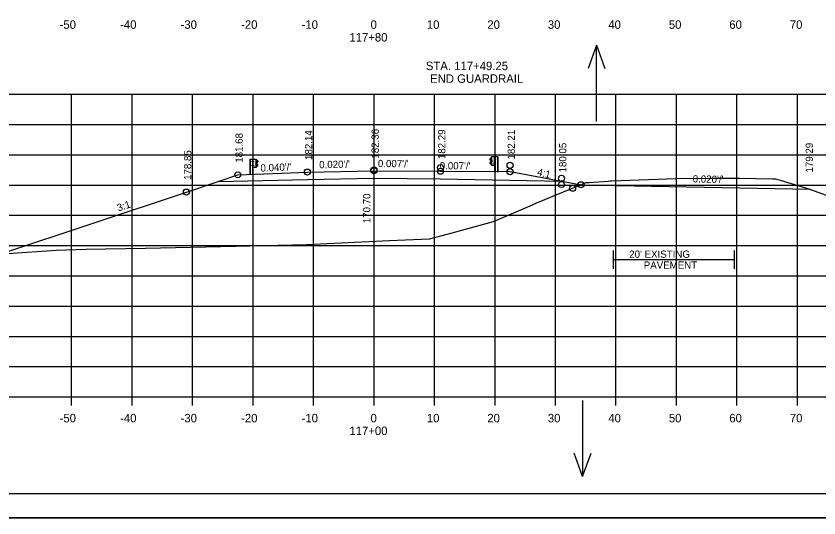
# Model space of a CAD drawing. Extents: x 915787 to 919910, y 133456 to 136717.
# Drawn here: x 916354.8 to 916487.5, y 135376.1 to 135459 of the extents above; entities that cross this region are included whole.
import ezdxf

# ---------------------------------------------------------------- set-up
doc = ezdxf.new("R2010")
doc.units = 0
for name, color, linetype in [('R_Axis', 7, 'Continuous'), ('R_Axis Annot', 7, 'Continuous'), ('R_Border', 7, 'Continuous'), ('R_Drive', 7, 'Continuous'), ('R_Exist Surface', 7, 'Continuous'), ('R_Exist Surface Annot', 7, 'Continuous'), ('R_Fin Surface', 7, 'Continuous'), ('R_Grid', 7, 'Continuous'), ('R_No Plot', 7, 'Continuous'), ('R_Proposed Road', 7, 'Continuous'), ('R_Water', 7, 'Continuous'), ('R_Water Annot', 7, 'Continuous'), ('R_Xsect Elev', 7, 'Continuous'), ('R_Xsect Slope', 7, 'Continuous')]:
    doc.layers.add(name, color=color, linetype=linetype)

msp = doc.modelspace()

# ---------------------------------------------------------------- linework, layer by layer
at = {"layer": 'R_Axis'}
for p, q in [((916273.98, 135396.06), (916553.98, 135396.06)), ((916363.98, 135394.66), (916363.98, 135396.06)), ((916373.98, 135394.66), (916373.98, 135396.06)), ((916383.98, 135394.66), (916383.98, 135396.06)), ((916393.98, 135394.66), (916393.98, 135396.06)), ((916403.98, 135394.66), (916403.98, 135396.06)), ((916413.98, 135394.66), (916413.98, 135396.06)), ((916423.98, 135394.66), (916423.98, 135396.06)), ((916433.98, 135394.66), (916433.98, 135396.06)), ((916443.98, 135394.66), (916443.98, 135396.06)), ((916453.98, 135394.66), (916453.98, 135396.06)), ((916463.98, 135394.66), (916463.98, 135396.06)), ((916473.98, 135394.66), (916473.98, 135396.06)), ((916483.98, 135394.66), (916483.98, 135396.06))]:
    msp.add_line(p, q, dxfattribs=at)
at = {"layer": 'R_Border'}
msp.add_line((916572.16, 135380.06), (916255.98, 135380.06), dxfattribs=at)
at = {"layer": 'R_Exist Surface'}
msp.add_lwpolyline([(916353.45, 135419.75), (916361.45, 135420.29), (916366.41, 135420.44), (916376.19, 135420.61), (916391.14, 135420.98), (916402.82, 135421.24), (916416.55, 135421.87), (916423.16, 135422.2), (916426.28, 135423.02), (916433.75, 135425.02), (916440.16, 135427.79), (916441, 135428.16), (916441.3, 135428.27), (916449.05, 135431.45), (916449.53, 135431.49), (916452.66, 135431.7), (916453.04, 135431.73), (916453.21, 135431.73), (916463.91, 135432.13), (916469.42, 135432.17), (916474.44, 135432.21), (916479.84, 135432.08), (916480.34, 135432.07), (916481.09, 135431.86), (916485.87, 135430.42), (916489.6, 135429.03)], dxfattribs=at)
at = {"layer": 'R_Exist Surface Annot'}
for p, q in [((916453.53, 135420.24), (916453.53, 135417.24)), ((916473.53, 135420.24), (916473.53, 135417.24)), ((916453.53, 135418.74), (916473.53, 135418.74))]:
    msp.add_line(p, q, dxfattribs=at)
at = {"layer": 'R_Fin Surface'}
for points in [[(916352.3, 135419.68), (916382.97, 135429.9), (916388.22, 135431.65), (916391.47, 135432.74), (916402.97, 135433.2), (916413.97, 135433.42), (916424.97, 135433.34), (916436.47, 135433.27), (916448.21, 135431.1), (916486.06, 135430.35)], [(916388.22, 135431.65), (916402.97, 135431.95), (916413.97, 135432.17), (916424.97, 135432.09), (916445.02, 135431.69)]]:
    msp.add_lwpolyline(points, dxfattribs=at)
at = {"layer": 'R_Grid'}
for p, q in [((916273.98, 135446.06), (916553.98, 135446.06)), ((916363.98, 135396.06), (916363.98, 135446.06)), ((916373.98, 135396.06), (916373.98, 135446.06)), ((916383.98, 135396.06), (916383.98, 135446.06)), ((916393.98, 135396.06), (916393.98, 135446.06)), ((916403.98, 135396.06), (916403.98, 135446.06)), ((916413.98, 135396.06), (916413.98, 135446.06)), ((916423.98, 135396.06), (916423.98, 135446.06)), ((916433.98, 135396.06), (916433.98, 135446.06)), ((916443.98, 135396.06), (916443.98, 135446.06)), ((916453.98, 135396.06), (916453.98, 135446.06)), ((916463.98, 135396.06), (916463.98, 135446.06)), ((916473.98, 135396.06), (916473.98, 135446.06)), ((916483.98, 135396.06), (916483.98, 135446.06)), ((916273.98, 135441.06), (916553.98, 135441.06)), ((916273.98, 135436.06), (916553.98, 135436.06)), ((916273.98, 135431.06), (916553.98, 135431.06)), ((916273.98, 135426.06), (916553.98, 135426.06)), ((916273.98, 135421.06), (916553.98, 135421.06)), ((916273.98, 135416.06), (916553.98, 135416.06)), ((916273.98, 135411.06), (916553.98, 135411.06)), ((916273.98, 135406.06), (916553.98, 135406.06)), ((916273.98, 135401.06), (916553.98, 135401.06)), ((916273.98, 135396.06), (916553.98, 135396.06))]:
    msp.add_line(p, q, dxfattribs=at)
at = {"layer": 'R_No Plot'}
msp.add_line((916243.57, 135376.08), (916576.91, 135376.08), dxfattribs=at)
for points in [[(916243.57, 135589.41), (916576.91, 135589.41), (916576.91, 135376.07), (916243.57, 135376.07)], [(916489.9, 135585.52), (916489.9, 135575.64), (916525.63, 135575.64), (916525.63, 135572.72), (916548.83, 135572.72), (916548.83, 135549.5), (916572.16, 135549.5), (916572.16, 135380.06), (916255.98, 135380.06), (916255.98, 135585.52)]]:
    msp.add_lwpolyline(points, close=True, dxfattribs=at)
for centre in [(916402.97, 135433.2), (916402.97, 135433.2), (916413.97, 135433.56), (916413.97, 135433.42), (916424.97, 135433.93), (916424.97, 135433.34), (916436.47, 135434.31), (916436.47, 135433.27), (916391.47, 135432.74), (916391.47, 135432.74), (916444.97, 135432.18), (916444.97, 135431.14), (916446.81, 135430.53), (916448.21, 135431.1), (916382.97, 135429.9), (916382.97, 135429.9)]:
    msp.add_circle(centre, 0.5, dxfattribs=at)
at = {"layer": 'R_Proposed Road'}
for p, q in [((916393.47, 135435.33), (916393.47, 135432.81)), ((916393.5, 135435.33), (916393.5, 135432.81)), ((916393.87, 135434.92), (916393.87, 135435.01)), ((916393.93, 135435.03), (916393.88, 135435.03)), ((916393.93, 135435), (916393.88, 135435)), ((916393.93, 135434.93), (916393.88, 135434.93)), ((916393.93, 135434.9), (916393.88, 135434.9)), ((916393.93, 135434.93), (916393.89, 135434.93)), ((916394, 135435.33), (916393.93, 135435.33)), ((916393.93, 135434.9), (916393.93, 135435.03)), ((916393.97, 135432.81), (916393.97, 135435.33)), ((916394, 135435.33), (916393.99, 135435.33)), ((916394.05, 135434.96), (916394, 135434.96)), ((916394.01, 135435.02), (916394.06, 135435.02)), ((916394.01, 135434.9), (916394.06, 135434.9)), ((916394.06, 135435.02), (916394.06, 135434.9)), ((916394.5, 135433.96), (916394.5, 135435.32)), ((916394.64, 135435.11), (916394.53, 135435.17)), ((916394.63, 135435.1), (916394.54, 135435.15)), ((916394.76, 135434.99), (916394.63, 135435.1)), ((916394.77, 135435.01), (916394.64, 135435.11)), ((916433.14, 135435.38), (916433.27, 135435.48)), ((916433.32, 135435.13), (916433.15, 135435.23)), ((916433.16, 135435.36), (916433.29, 135435.47)), ((916433.33, 135435.15), (916433.16, 135435.26)), ((916433.17, 135434.8), (916433.32, 135434.9)), ((916433.27, 135435.48), (916433.38, 135435.54)), ((916433.29, 135435.47), (916433.38, 135435.52)), ((916433.35, 135434.95), (916433.35, 135435.08)), ((916433.38, 135434.95), (916433.38, 135435.08)), ((916433.42, 135434.33), (916433.42, 135435.69)), ((916433.43, 135434.95), (916433.43, 135435.07)), ((916433.43, 135435.07), (916433.48, 135435.07)), ((916433.43, 135435.04), (916433.48, 135435.04)), ((916433.43, 135434.98), (916433.47, 135434.98)), ((916433.43, 135434.98), (916433.48, 135434.98)), ((916433.43, 135434.95), (916433.48, 135434.95)), ((916433.48, 135434.96), (916433.48, 135435.06)), ((916433.91, 135435.39), (916433.86, 135435.39)), ((916433.86, 135435.39), (916433.86, 135435.27)), ((916433.86, 135435.33), (916433.92, 135435.33)), ((916433.91, 135435.27), (916433.86, 135435.27)), ((916433.92, 135435.7), (916433.92, 135435.7)), ((916433.92, 135435.7), (916433.98, 135435.7)), ((916433.95, 135433.18), (916433.95, 135435.7)), ((916433.99, 135435.27), (916433.99, 135435.4)), ((916433.99, 135435.4), (916434.03, 135435.4)), ((916433.99, 135435.37), (916434.03, 135435.37)), ((916433.99, 135435.3), (916434.03, 135435.3)), ((916433.99, 135435.3), (916434.03, 135435.3)), ((916433.99, 135435.27), (916434.04, 135435.27)), ((916434.04, 135435.29), (916434.04, 135435.38)), ((916434.41, 135435.7), (916434.41, 135433.18)), ((916434.44, 135435.7), (916434.44, 135433.18)), ((916393.86, 135434.23), (916393.86, 135434.32)), ((916393.92, 135434.34), (916393.87, 135434.34)), ((916393.92, 135434.31), (916393.87, 135434.31)), ((916393.92, 135434.24), (916393.87, 135434.24)), ((916393.92, 135434.21), (916393.87, 135434.21)), ((916393.92, 135434.24), (916393.88, 135434.24)), ((916393.92, 135434.21), (916393.92, 135434.34)), ((916394, 135433.96), (916393.96, 135433.96)), ((916394.05, 135434.27), (916394, 135434.27)), ((916394.06, 135434.34), (916394.01, 135434.34)), ((916394.06, 135434.21), (916394.01, 135434.21)), ((916394.06, 135434.21), (916394.06, 135434.34)), ((916394.43, 135434.59), (916394.43, 135434.69)), ((916394.49, 135434.7), (916394.44, 135434.7)), ((916394.49, 135434.67), (916394.44, 135434.67)), ((916394.49, 135434.61), (916394.44, 135434.61)), ((916394.49, 135434.61), (916394.44, 135434.61)), ((916394.49, 135434.58), (916394.44, 135434.58)), ((916394.49, 135434.58), (916394.49, 135434.7)), ((916394.53, 135434.12), (916394.63, 135434.18)), ((916394.53, 135434.1), (916394.65, 135434.16)), ((916394.54, 135434.58), (916394.54, 135434.71)), ((916394.56, 135434.58), (916394.56, 135434.71)), ((916394.58, 135434.78), (916394.76, 135434.89)), ((916394.73, 135434.41), (916394.58, 135434.51)), ((916394.75, 135434.43), (916394.59, 135434.53)), ((916394.6, 135434.76), (916394.77, 135434.86)), ((916394.63, 135434.18), (916394.76, 135434.29)), ((916394.65, 135434.16), (916394.77, 135434.27)), ((916433.27, 135434.53), (916433.14, 135434.64)), ((916433.28, 135434.55), (916433.15, 135434.66)), ((916433.18, 135434.78), (916433.34, 135434.88)), ((916433.38, 135434.47), (916433.27, 135434.53)), ((916433.39, 135434.49), (916433.28, 135434.55)), ((916433.86, 135434.58), (916433.86, 135434.71)), ((916433.86, 135434.71), (916433.91, 135434.71)), ((916433.86, 135434.64), (916433.92, 135434.64)), ((916433.86, 135434.58), (916433.91, 135434.58)), ((916433.92, 135434.33), (916433.95, 135434.33)), ((916434, 135434.58), (916434, 135434.71)), ((916434, 135434.71), (916434.04, 135434.71)), ((916434, 135434.68), (916434.05, 135434.68)), ((916434, 135434.61), (916434.04, 135434.61)), ((916434, 135434.61), (916434.05, 135434.61)), ((916434, 135434.58), (916434.05, 135434.58)), ((916434.05, 135434.6), (916434.05, 135434.69))]:
    msp.add_line(p, q, dxfattribs=at)
for points in [[(916393.47, 135435.33), (916393.93, 135435.33), (916393.93, 135432.81)], [(916434.44, 135435.7), (916433.98, 135435.7), (916433.99, 135433.18)]]:
    msp.add_lwpolyline(points, dxfattribs=at)
for points in [[(916393.87, 135434.99), (916393.87, 135434.93), (916393.85, 135434.93), (916393.85, 135434.99)], [(916393.93, 135435.05), (916393.93, 135434.88), (916393.94, 135434.88), (916393.94, 135435.05)], [(916394.52, 135435.33), (916394.52, 135433.96), (916394, 135433.96), (916394, 135435.33)], [(916394.05, 135435.02), (916394.05, 135434.9), (916394, 135434.9), (916394, 135435.02)], [(916433.39, 135435.7), (916433.39, 135434.33), (916433.92, 135434.33), (916433.92, 135435.7)], [(916433.43, 135435.09), (916433.43, 135434.93), (916433.42, 135434.93), (916433.42, 135435.09)], [(916433.49, 135435.04), (916433.49, 135434.98), (916433.51, 135434.98), (916433.51, 135435.04)], [(916433.86, 135435.39), (916433.86, 135435.27), (916433.92, 135435.27), (916433.92, 135435.39)], [(916433.99, 135435.42), (916433.99, 135435.25), (916433.98, 135435.25), (916433.98, 135435.42)], [(916434.04, 135435.36), (916434.04, 135435.3), (916434.07, 135435.3), (916434.07, 135435.36)], [(916393.86, 135434.31), (916393.86, 135434.24), (916393.84, 135434.24), (916393.84, 135434.31)], [(916393.92, 135434.36), (916393.92, 135434.19), (916393.93, 135434.19), (916393.93, 135434.36)], [(916394.05, 135434.34), (916394.05, 135434.21), (916394, 135434.21), (916394, 135434.34)], [(916394.43, 135434.67), (916394.43, 135434.61), (916394.4, 135434.61), (916394.4, 135434.67)], [(916394.48, 135434.72), (916394.48, 135434.56), (916394.49, 135434.56), (916394.49, 135434.72)], [(916433.86, 135434.71), (916433.86, 135434.58), (916433.92, 135434.58), (916433.92, 135434.71)], [(916434, 135434.73), (916434, 135434.56), (916433.99, 135434.56), (916433.99, 135434.73)], [(916434.05, 135434.68), (916434.05, 135434.61), (916434.08, 135434.61), (916434.08, 135434.68)]]:
    msp.add_lwpolyline(points, close=True, dxfattribs=at)
for centre, radius, start, end in [((916393.9, 135435.01), 0.022, 134.5745, 222.2244), ((916393.97, 135434.96), 0.0922, 159.7423, 200.2577), ((916393.9, 135434.92), 0.025, 140.9334, 216.6234), ((916394.73, 135434.94), 0.062, 299.2499, 57.9783), ((916394.73, 135434.94), 0.0856, 299.2499, 57.9783), ((916433.19, 135435.31), 0.0856, 122.0217, 240.7501), ((916433.19, 135435.31), 0.062, 122.0217, 240.7501), ((916433.36, 135435.01), 0.0453, 93.9303, 257.0446), ((916433.29, 135435.07), 0.0622, 4.9556, 61.894), ((916433.29, 135435.07), 0.0865, 4.9556, 61.894), ((916433.31, 135434.94), 0.0462, 293.1464, 8.2196), ((916433.31, 135434.94), 0.0703, 293.1464, 8.2196), ((916433.46, 135435.06), 0.022, 317.7756, 45.4255), ((916433.39, 135435.01), 0.0922, 339.7423, 20.2577), ((916433.46, 135434.96), 0.025, 323.3766, 39.0666), ((916434.02, 135435.38), 0.022, 317.7756, 45.4255), ((916433.95, 135435.33), 0.0922, 339.7423, 20.2577), ((916434.02, 135435.28), 0.025, 323.3766, 39.0666), ((916393.89, 135434.32), 0.022, 134.5745, 222.2244), ((916393.96, 135434.27), 0.0922, 159.7423, 200.2577), ((916393.89, 135434.23), 0.025, 140.9334, 216.6234), ((916394.45, 135434.69), 0.022, 134.5745, 222.2244), ((916394.52, 135434.64), 0.0922, 159.7423, 200.2577), ((916394.46, 135434.59), 0.025, 140.9334, 216.6234), ((916394.63, 135434.7), 0.0865, 118.106, 175.0444), ((916394.61, 135434.57), 0.0703, 171.7804, 246.8536), ((916394.63, 135434.7), 0.0622, 118.106, 175.0444), ((916394.56, 135434.64), 0.0453, 282.9554, 86.0697), ((916394.61, 135434.57), 0.0462, 171.7804, 246.8536), ((916394.69, 135434.34), 0.0854, 325.2184, 59.12), ((916394.69, 135434.34), 0.109, 325.2184, 59.12), ((916433.22, 135434.7), 0.109, 120.88, 214.7816), ((916433.22, 135434.7), 0.0854, 120.88, 214.7816), ((916434.03, 135434.69), 0.022, 317.7756, 45.4255), ((916433.96, 135434.64), 0.0922, 339.7423, 20.2577), ((916434.03, 135434.6), 0.025, 323.3766, 39.0666)]:
    msp.add_arc(centre, radius, start, end, dxfattribs=at)
at = {"layer": 'R_Water'}
msp.add_line((916448.21, 135431.1), (916486.06, 135430.35), dxfattribs=at)
at = {"layer": 'R_Water Annot'}
for p, q in [((916450.76, 135454.14), (916449.36, 135450.29)), ((916450.76, 135441.57), (916450.76, 135454.14)), ((916450.76, 135454.14), (916452.16, 135450.29)), ((916448.47, 135395.48), (916448.47, 135382.91)), ((916448.47, 135382.91), (916447.07, 135386.76)), ((916448.47, 135382.91), (916449.87, 135386.76))]:
    msp.add_line(p, q, dxfattribs=at)

# ---------------------------------------------------------------- texts
at = {"layer": 'R_Axis Annot'}
for s, p in [('-50', (916362.01, 135456.86)), ('-40', (916372.01, 135456.86)), ('-30', (916382.01, 135456.86)), ('-20', (916392.01, 135456.86)), ('-10', (916402.01, 135456.86)), ('0', (916413.41, 135456.86)), ('10', (916422.71, 135456.86)), ('20', (916432.71, 135456.86)), ('30', (916442.71, 135456.86)), ('40', (916452.71, 135456.86)), ('50', (916462.71, 135456.86)), ('60', (916472.71, 135456.86)), ('70', (916482.71, 135456.86)), ('117+80', (916409.91, 135454.76)), ('-50', (916362.01, 135391.86)), ('-40', (916372.01, 135391.86)), ('-30', (916382.01, 135391.86)), ('-20', (916392.01, 135391.86)), ('-10', (916402.01, 135391.86)), ('0', (916413.41, 135391.86)), ('10', (916422.71, 135391.86)), ('20', (916432.71, 135391.86)), ('30', (916442.71, 135391.86)), ('40', (916452.71, 135391.86)), ('50', (916462.71, 135391.86)), ('60', (916472.71, 135391.86)), ('70', (916482.71, 135391.86)), ('117+00', (916409.91, 135389.76))]:
    msp.add_text(s, height=1.4, dxfattribs=at).set_placement(p)
at = {"layer": 'R_Drive'}
for s, p in [('STA. 117+49.25', (916422.55, 135450.04)), ('END GUARDRAIL', (916423.25, 135447.94))]:
    msp.add_text(s, height=1.4, dxfattribs=at).set_placement(p)
at = {"layer": 'R_Exist Surface Annot'}
for s, p in [("20' EXISTING", (916456.17, 135419.04)), ('PAVEMENT', (916458.57, 135417.24))]:
    msp.add_text(s, height=1.2, dxfattribs=at).set_placement(p)
at = {"layer": 'R_Xsect Elev'}
for s, p in [('182.36', (916414.77, 135435.42)), ('181.68', (916392.27, 135434.74)), ('182.14', (916403.77, 135435.2)), ('182.29', (916425.77, 135435.34)), ('182.21', (916437.27, 135435.27)), ('180.05', (916445.77, 135433.14)), ('179.29', (916486.53, 135433.13)), ('178.85', (916383.77, 135431.9)), ('170.70', (916413.38, 135424.75))]:
    msp.add_text(s, height=1.2, rotation=90, dxfattribs=at).set_placement(p)
at = {"layer": 'R_Xsect Slope'}
for s, rotation, p in [("0.020'/'", 1.1458, (916404.93, 135433.82)), ("0.007'/'", 359.6265, (916414.62, 135434.02)), ("0.007'/'", 359.6265, (916424.84, 135433.66)), ("0.040'/'", 2.2906, (916395.24, 135433.27)), ('4:1', 345.9638, (916440.85, 135432.69)), ("0.020'/'", 358.8542, (916466.65, 135431.49)), ('3:1', 18.4349, (916371.73, 135426.68))]:
    msp.add_text(s, height=1.2, rotation=rotation, dxfattribs=at).set_placement(p)

doc.saveas('drawing.dxf')
